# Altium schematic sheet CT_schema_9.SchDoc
size 274 x 160 mm
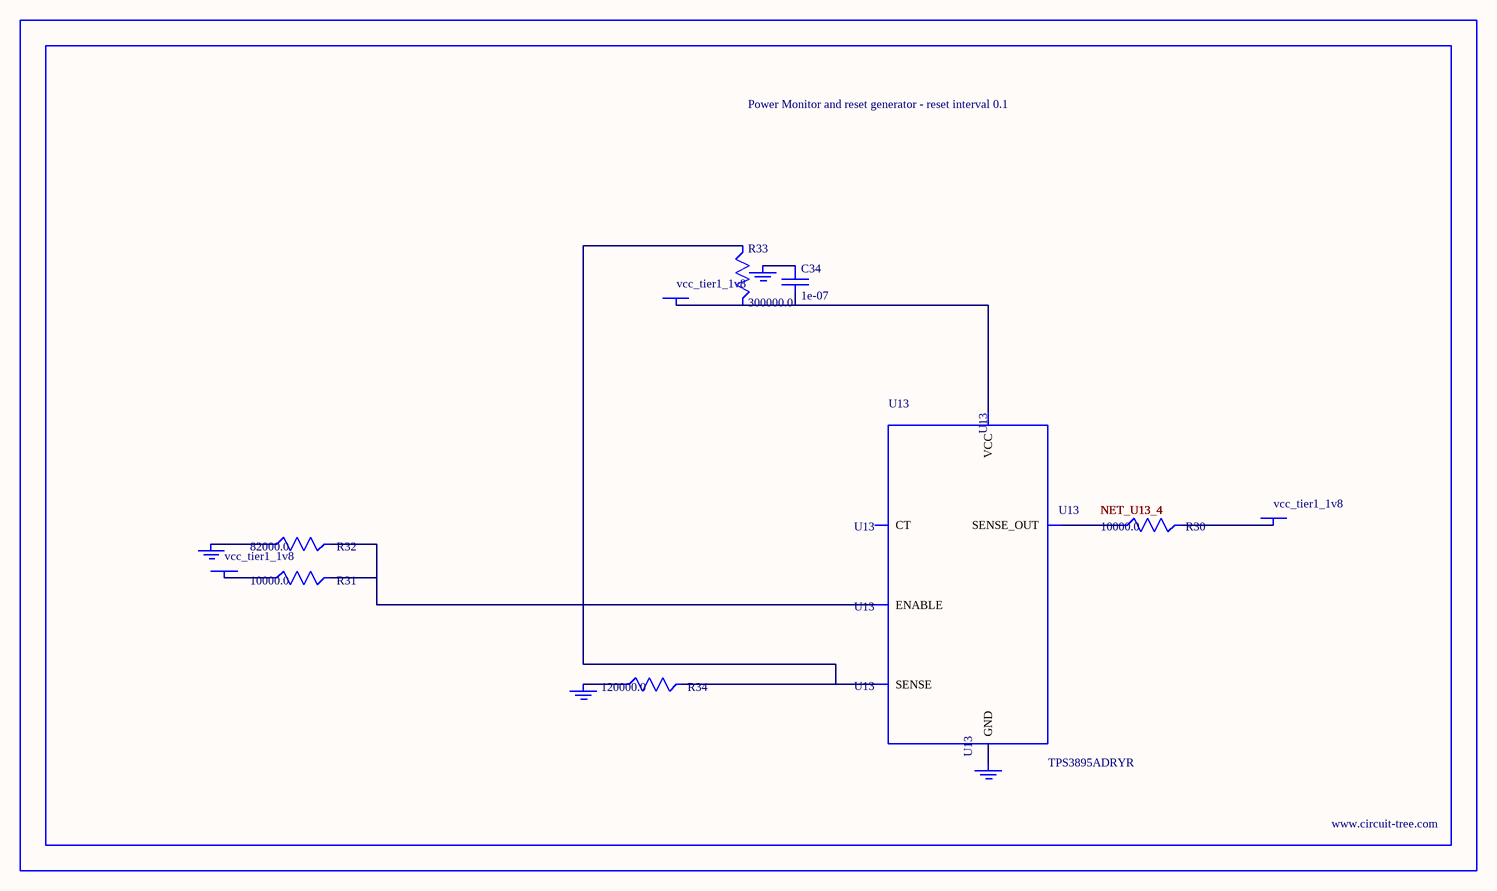
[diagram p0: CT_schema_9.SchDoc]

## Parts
BORDER8  (no value)
C34  1e-07  [C0402]
GND_INSTANCE_8_0  (no value)
GND_INSTANCE_8_1  (no value)
GND_INSTANCE_8_2  (no value)
GND_INSTANCE_8_3  (no value)
POWER_INSTANCE_8_0  vcc_tier1_1v8
POWER_INSTANCE_8_1  vcc_tier1_1v8
POWER_INSTANCE_8_2  vcc_tier1_1v8
R30  10000.0  [R0603]
R31  10000.0  [R0603]
R32  82000.0  [R0603]
R33  300000.0  [R0603]
R34  120000.0  [R0603]
U13  TPS3895ADRYR  [SON-6]

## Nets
NetC34_1: C34.1 GND_INSTANCE_8_2.0(GND)
NetC34_2: C34.2 POWER_INSTANCE_8_2.0(PWR) R33.2 U13.6(VCC)
NetGND_INSTANCE_8_0_0: GND_INSTANCE_8_0.0(GND) R32.1
NetGND_INSTANCE_8_1_0: GND_INSTANCE_8_1.0(GND) R34.1
NetGND_INSTANCE_8_3_0: GND_INSTANCE_8_3.0(GND) U13.2(GND)
NetPOWER_INSTANCE_8_0_0: POWER_INSTANCE_8_0.0(PWR) R31.1
NetPOWER_INSTANCE_8_1_0: POWER_INSTANCE_8_1.0(PWR) R30.2
NetR30_1: R30.1 U13.4(SENSE_OUT)
NetR31_2: R31.2 R32.2 U13.1(ENABLE)
NetR33_1: R33.1 R34.2 U13.3(SENSE)

Not connected (* = marked no-connect by the designer): U13 5(CT)

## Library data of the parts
BORDER8 = BORDER_PAGE8
C34 = C0402C104K3RACTU
GND_INSTANCE_8_0-GND_INSTANCE_8_3 = GND
POWER_INSTANCE_8_0-POWER_INSTANCE_8_2 = PWR
R30 R31 = RC0603JR-0710KL
R32 = RC0603JR-0782KL
R33 = RC0603JR-07300KL
R34 = RC0603JR-07120KL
